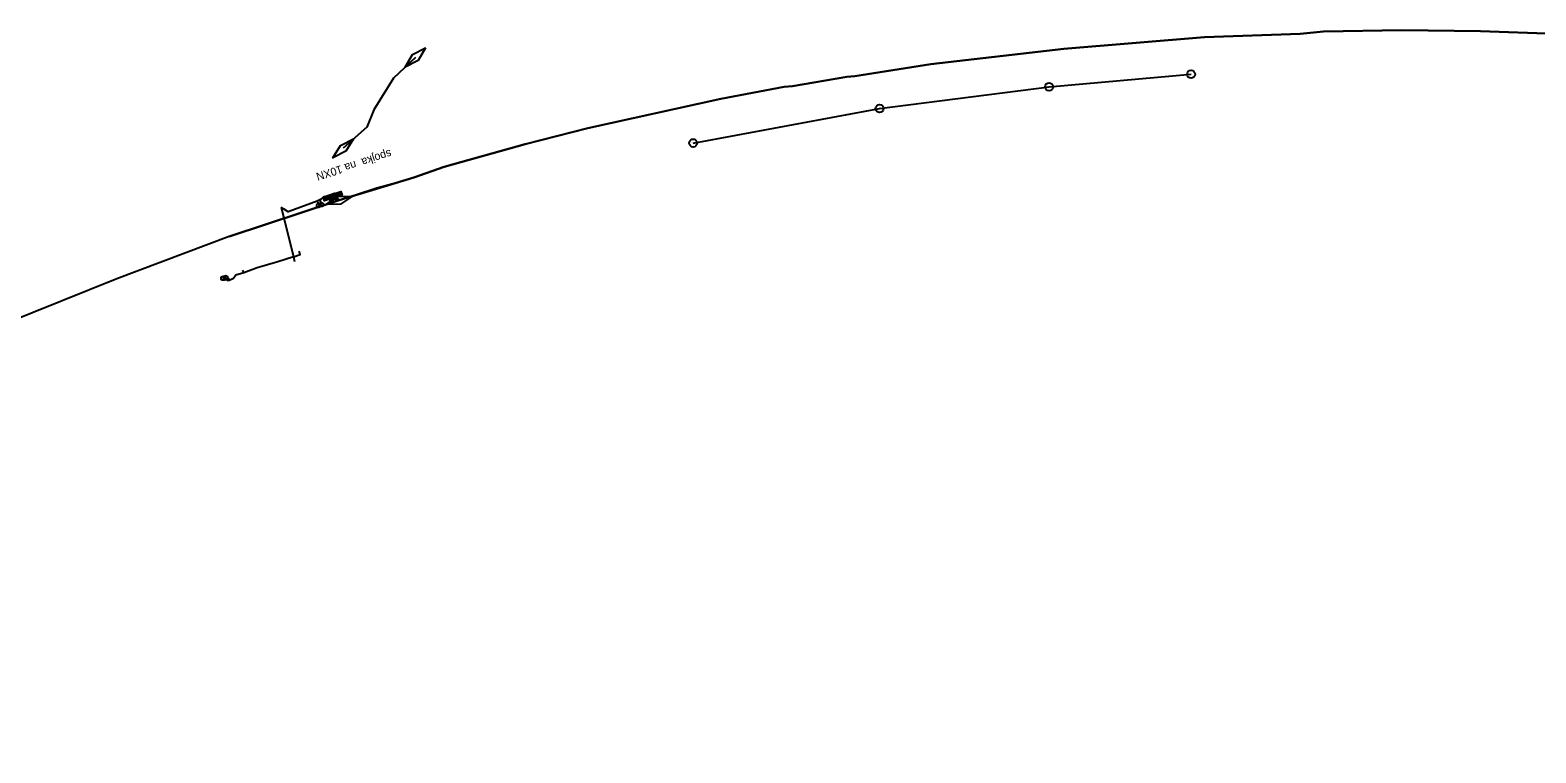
# Model space of a CAD drawing. Extents: x -748507 to -687366, y -1057342 to -1024924.
# Drawn here: x -745197.8 to -744821.4, y -1033540.9 to -1033360.2 of the extents above; entities that cross this region are included whole.
import ezdxf

# ---------------------------------------------------------------- set-up
doc = ezdxf.new("R2010")
doc.units = 0
for name, color, linetype in [('6kV - SŽDC', 7, 'Continuous'), ('DK + TKK - SŽDC', 7, 'Continuous'), ('kanalizace ČD', 7, 'Continuous'), ('TK+DOK_Pha Holešovice - Kralupy', 7, 'Continuous')]:
    doc.layers.add(name, color=color, linetype=linetype)

msp = doc.modelspace()

# ---------------------------------------------------------------- linework, layer by layer
at = {"layer": '6kV - SŽDC'}
for points in [[(-745098.99, -1033364.59), (-745100.83, -1033367.72), (-745104.05, -1033369.41), (-745102.21, -1033366.28), (-745098.99, -1033364.59)], [(-745101.52, -1033367), (-745106.98, -1033372.2), (-745111.92, -1033380.07), (-745113.68, -1033384.43), (-745119.57, -1033389.72)], [(-745116.97, -1033387.38), (-745118.9, -1033390.46), (-745122.17, -1033392.06), (-745120.24, -1033388.98), (-745116.97, -1033387.38)]]:
    msp.add_lwpolyline(points, dxfattribs=at)
at = {"layer": 'DK + TKK - SŽDC'}
for p, q in [((-745125.08, -1033403.8), (-745124.98, -1033403.8)), ((-745124.49, -1033401.88), (-745124.54, -1033401.96)), ((-745123.99, -1033401.71), (-745124.38, -1033402.47)), ((-745123.49, -1033401.55), (-745124.13, -1033402.81)), ((-745122.98, -1033401.39), (-745123.62, -1033402.65)), ((-745122.48, -1033401.22), (-745123.12, -1033402.48)), ((-745122.91, -1033401.43), (-745122.95, -1033401.52)), ((-745122.4, -1033401.26), (-745122.79, -1033402.02)), ((-745121.97, -1033401.06), (-745122.61, -1033402.32)), ((-745121.9, -1033401.1), (-745122.54, -1033402.36)), ((-745121.63, -1033401.21), (-745122.11, -1033402.15)), ((-745121.39, -1033400.94), (-745122.03, -1033402.2)), ((-745121.47, -1033401.71), (-745121.61, -1033401.99)), ((-745120.89, -1033400.77), (-745121.53, -1033402.03)), ((-745120.38, -1033400.61), (-745121.03, -1033401.87)), ((-745120.04, -1033400.76), (-745120.52, -1033401.7)), ((-745119.88, -1033401.26), (-745120.02, -1033401.54)), ((-745125.74, -1033404.01), (-745125.64, -1033404.01)), ((-745149.55, -1033422.2), (-745149.65, -1033422.24)), ((-745148.88, -1033422.01), (-745148.98, -1033422.05))]:
    msp.add_line(p, q, dxfattribs=at)
for points in [[(-745148.06, -1033411.76), (-745120.55, -1033402.72), (-745101.95, -1033396.99), (-745094.31, -1033394.37), (-745074.06, -1033388.71), (-745058.41, -1033384.68), (-745025.15, -1033377.36), (-745009.34, -1033374.33), (-745007.3, -1033374.14), (-744993.65, -1033371.82), (-744991.72, -1033371.68), (-744972.67, -1033368.71), (-744939.44, -1033364.84), (-744904.29, -1033361.94), (-744880.4, -1033361.05), (-744874.49, -1033360.49), (-744854.99, -1033360.16), (-744835.31, -1033360.4), (-744816.56, -1033361.07), (-744791.79, -1033362.59), (-744765.65, -1033364.96)], [(-745105.91, -1033398.23), (-745111.18, -1033399.71), (-745116.23, -1033401.31), (-745120.6, -1033402.65)], [(-745120.6, -1033402.65), (-745123.06, -1033402.26), (-745124.33, -1033401.79), (-745125.37, -1033402.63), (-745126.1, -1033402.93), (-745133.32, -1033405.6), (-745134.46, -1033404.81), (-745135.08, -1033404.44)], [(-745126.1, -1033402.93), (-745125.77, -1033403.4), (-745125.69, -1033404.01)], [(-745125.37, -1033402.63), (-745125.28, -1033403.18), (-745125.03, -1033403.8)], [(-745121.4, -1033401.92), (-745124.25, -1033402.85), (-745124.56, -1033401.9), (-745121.71, -1033400.97), (-745121.4, -1033401.92)], [(-745124.33, -1033401.79), (-745124.28, -1033402.49)], [(-745122.04, -1033403.18), (-745122.83, -1033402.39), (-745122.99, -1033403.49)], [(-745119.81, -1033401.47), (-745122.66, -1033402.4), (-745122.97, -1033401.45), (-745120.12, -1033400.52), (-745119.81, -1033401.47)], [(-745120.45, -1033402.73), (-745121.23, -1033401.94), (-745121.4, -1033403.04)], [(-745135.08, -1033404.44), (-745132.02, -1033416.88)], [(-745148.06, -1033411.76), (-745176.11, -1033422.32), (-745203.93, -1033433.49)], [(-745132.02, -1033416.88), (-745135.92, -1033418.1), (-745141.07, -1033419.62), (-745144.4, -1033420.85), (-745146.38, -1033421.42), (-745147.02, -1033422.3)], [(-745132.02, -1033416.88), (-745130.32, -1033416.24), (-745130.56, -1033415.45)], [(-745132.02, -1033416.88), (-745131.7, -1033417.99)], [(-745148.59, -1033422.58), (-745149.11, -1033422.7), (-745149.6, -1033422.22)], [(-745148.24, -1033422.89), (-745148.59, -1033422.58), (-745148.93, -1033422.03)], [(-745148.24, -1033422.89), (-745148.25, -1033422.35), (-745147.98, -1033422.17)], [(-745147.02, -1033422.3), (-745148.24, -1033422.89)], [(-745144.4, -1033420.85), (-745144.66, -1033420.19)]]:
    msp.add_lwpolyline(points, dxfattribs=at)
for points in [[(-745121.4, -1033401.92), (-745124.25, -1033402.85), (-745124.56, -1033401.9), (-745121.71, -1033400.97)], [(-745119.81, -1033401.47), (-745122.66, -1033402.4), (-745122.97, -1033401.45), (-745120.12, -1033400.52)]]:
    msp.add_lwpolyline(points, close=True, dxfattribs=at)
for centre in [(-745125.69, -1033404.01), (-745125.03, -1033403.8), (-745149.6, -1033422.22), (-745148.93, -1033422.03)]:
    msp.add_circle(centre, 0.5, dxfattribs=at)
at = {"layer": 'kanalizace ČD'}
msp.add_lwpolyline([(-745032.09, -1033388.39), (-744985.48, -1033379.79), (-744943.14, -1033374.34), (-744907.64, -1033371.21)], dxfattribs=at)
for centre in [(-744943.14, -1033374.34), (-744907.64, -1033371.21), (-744985.48, -1033379.79), (-745032.09, -1033388.39)]:
    msp.add_circle(centre, 1, dxfattribs=at)
at = {"layer": 'TK+DOK_Pha Holešovice - Kralupy'}
for points in [[(-744835.31, -1033360.4), (-744854.99, -1033360.16), (-744874.49, -1033360.49), (-744880.4, -1033361.05), (-744904.29, -1033361.94), (-744939.44, -1033364.84), (-744972.67, -1033368.71), (-744991.72, -1033371.68), (-744993.65, -1033371.82), (-745007.3, -1033374.14), (-745009.34, -1033374.33), (-745025.15, -1033377.36), (-745058.41, -1033384.68), (-745074.06, -1033388.71), (-745094.31, -1033394.37), (-745101.95, -1033396.99), (-745120.55, -1033402.72), (-745148.06, -1033411.76), (-745176.11, -1033422.32), (-745203.93, -1033433.49)], [(-744715.49, -1033371.53), (-744723.75, -1033370.27), (-744740.9, -1033367.82), (-744765.65, -1033364.96), (-744791.79, -1033362.59), (-744816.56, -1033361.07), (-744835.31, -1033360.4), (-744854.99, -1033360.16), (-744874.49, -1033360.49), (-744880.4, -1033361.05), (-744904.29, -1033361.94), (-744939.44, -1033364.84), (-744972.67, -1033368.71), (-744991.72, -1033371.68), (-744993.65, -1033371.82), (-745007.3, -1033374.14), (-745009.34, -1033374.33), (-745025.15, -1033377.36), (-745058.41, -1033384.68), (-745074.06, -1033388.71), (-745094.31, -1033394.37), (-745101.95, -1033396.99), (-745120.55, -1033402.72)], [(-744816.56, -1033361.07), (-744835.31, -1033360.4)], [(-745120.55, -1033402.72), (-745148.06, -1033411.76), (-745176.11, -1033422.32), (-745203.93, -1033433.49), (-745229.78, -1033443.94), (-745263.36, -1033457.66), (-745292.98, -1033469.66), (-745322.7, -1033481.81), (-745349.8, -1033492.68), (-745355.67, -1033495.12), (-745376.24, -1033503.59), (-745400.08, -1033513.57), (-745427.68, -1033524.27), (-745452.16, -1033534.47), (-745459.47, -1033537.75), (-745467.39, -1033540.91)], [(-745117.22, -1033401.66), (-745120.25, -1033403.68), (-745123.89, -1033403.79), (-745120.86, -1033401.77), (-745117.22, -1033401.66)]]:
    msp.add_lwpolyline(points, dxfattribs=at)

# ---------------------------------------------------------------- texts
msp.add_text('spojka  na 10XN', height=2, rotation=197.659, dxfattribs=at).set_placement((-745107.83, -1033390))

doc.saveas('drawing.dxf')
